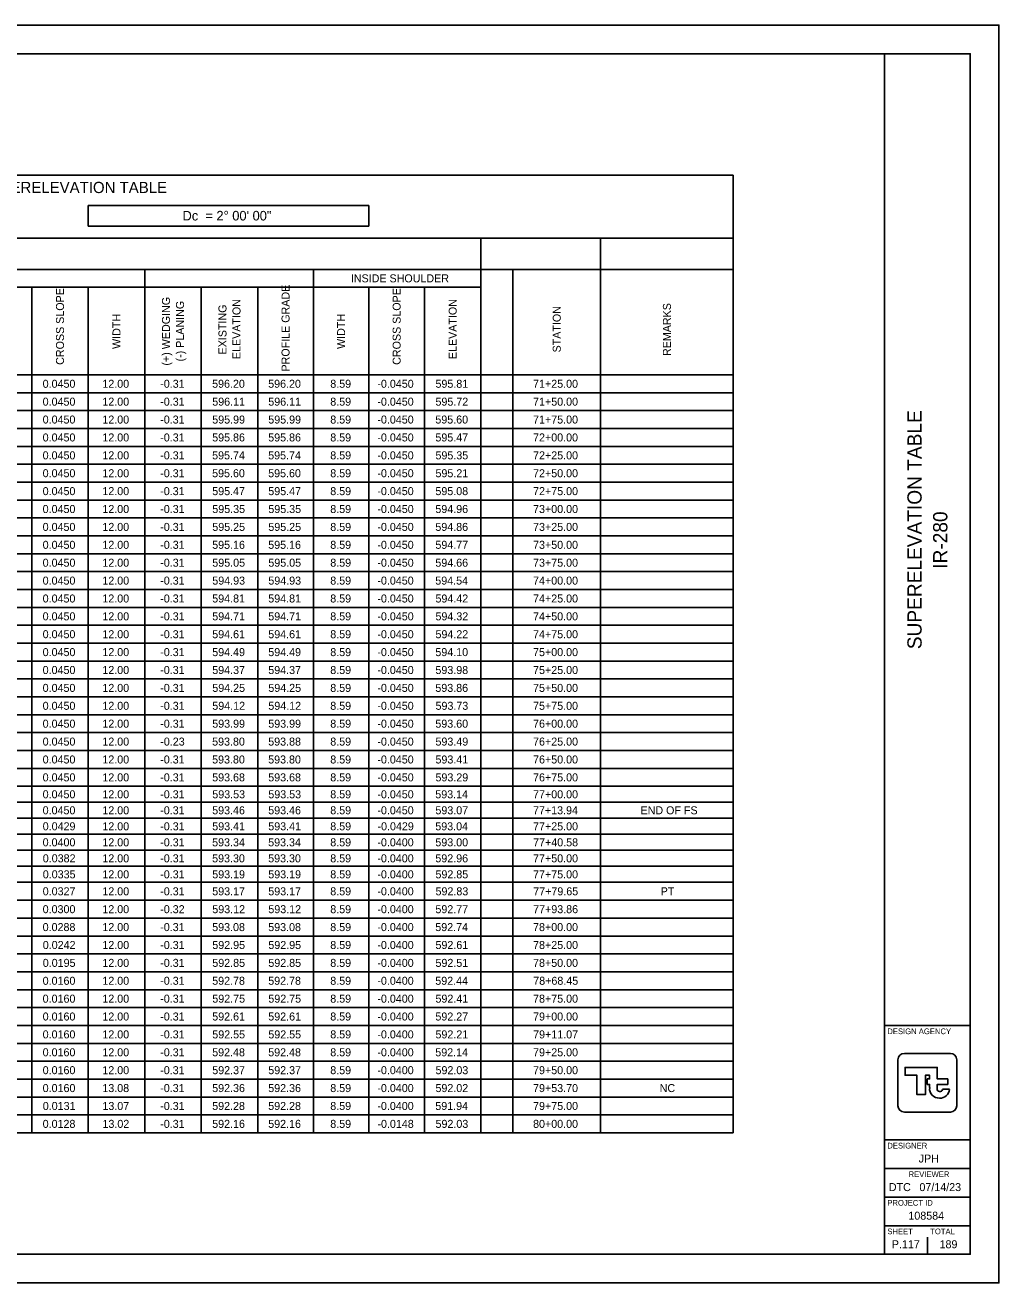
# Model space of a CAD drawing. Extents: x 0 to 34, y 0 to 22.
# Drawn here: x 16.97 to 34, y 0 to 22 of the extents above; entities that cross this region are included whole.
import ezdxf

# ---------------------------------------------------------------- set-up
doc = ezdxf.new("R2010")
doc.units = 0
for name, color, linetype in [('SH_Border', 7, 'Continuous'), ('SH_Cut_Line', 7, 'Continuous'), ('SH_Data', 7, 'Continuous'), ('SH_Text', 7, 'Continuous')]:
    doc.layers.add(name, color=color, linetype=linetype)

msp = doc.modelspace()

# ---------------------------------------------------------------- linework, layer by layer
at = {"layer": 'SH_Border'}
for p, q in [((32, 0.5), (32, 21.5)), ((32, 4.5), (33.5, 4.5)), ((32, 2.5), (33.5, 2.5)), ((32, 2), (33.5, 2)), ((32, 1.5), (33.5, 1.5)), ((32, 1), (33.5, 1))]:
    msp.add_line(p, q, dxfattribs=at)
msp.add_lwpolyline([(1.5, 21.5), (33.5, 21.5), (33.5, 0.5), (1.5, 0.5)], close=True, dxfattribs=at)
at = {"layer": 'SH_Cut_Line'}
msp.add_lwpolyline([(0, 0), (34, 0), (34, 22), (0, 22)], close=True, dxfattribs=at)
at = {"layer": 'SH_Data'}
for p, q in [((32.75, 3.5), (32.75, 3.5)), ((32.791, 3.415), (32.791, 3.415)), ((33.136, 3.385), (33.015, 3.385)), ((32.375, 0.675), (32.375, 0.675)), ((32.75, 0.5), (32.75, 0.8))]:
    msp.add_line(p, q, dxfattribs=at)
for points in [[(32.348, 4.014), (33.152, 4.014)], [(32.236, 3.099), (32.236, 3.901)], [(32.922, 3.399), (32.922, 3.47), (33.107, 3.47), (33.107, 3.568), (32.922, 3.568), (32.922, 3.768), (32.361, 3.768), (32.361, 3.632), (32.566, 3.632), (32.566, 3.294), (32.715, 3.294), (32.715, 3.63), (32.79, 3.63), (32.79, 3.568), (32.748, 3.568), (32.748, 3.47), (32.79, 3.47), (32.79, 3.415), (32.791, 3.415)], [(33.264, 3.901), (33.264, 3.099)], [(33.152, 2.986), (32.348, 2.986)]]:
    msp.add_lwpolyline(points, dxfattribs=at)
for centre, radius, start, end in [((32.348, 3.901), 0.113, 90, 180), ((33.152, 3.901), 0.113, 360, 90), ((32.949, 3.392), 0.16, 171.8856, 274.8323), ((32.968, 3.392), 0.0473, 171.8856, 350.9243), ((32.976, 3.392), 0.16, 265.1677, 357.3201), ((32.348, 3.099), 0.113, 180, 270), ((33.152, 3.099), 0.113, 270, 360)]:
    msp.add_arc(centre, radius, start, end, dxfattribs=at)
at = {"layer": 'SH_Text'}
for p, q in [((4.14, 19.375), (29.356, 19.375)), ((29.356, 19.375), (29.356, 2.624)), ((18.074, 18.848), (22.982, 18.848)), ((18.074, 18.848), (18.074, 18.486)), ((22.982, 18.848), (22.982, 18.486)), ((18.074, 18.486), (22.982, 18.486)), ((4.14, 18.271), (29.356, 18.271)), ((24.942, 18.271), (24.942, 2.624)), ((27.034, 18.271), (27.034, 2.624)), ((4.14, 17.728), (29.356, 17.728)), ((19.062, 17.728), (19.062, 2.624)), ((22.011, 17.728), (22.011, 2.624)), ((25.502, 17.728), (25.502, 2.624)), ((4.14, 17.415), (24.942, 17.415)), ((17.086, 17.415), (17.086, 2.624)), ((18.074, 17.415), (18.074, 2.624)), ((20.051, 17.415), (20.051, 2.624)), ((21.039, 17.415), (21.039, 2.624)), ((22.982, 17.415), (22.982, 2.624)), ((23.954, 17.415), (23.954, 2.624)), ((4.14, 15.883), (29.356, 15.883)), ((4.14, 15.57), (29.356, 15.57)), ((4.14, 15.257), (29.356, 15.257)), ((4.14, 14.944), (29.356, 14.944)), ((4.14, 14.631), (29.356, 14.631)), ((4.14, 14.319), (29.356, 14.319)), ((4.14, 14.006), (29.356, 14.006)), ((4.14, 13.693), (29.356, 13.693)), ((4.14, 13.38), (29.356, 13.38)), ((4.14, 13.067), (29.356, 13.067)), ((4.14, 12.754), (29.356, 12.754)), ((4.14, 12.441), (29.356, 12.441)), ((4.14, 12.128), (29.356, 12.128)), ((4.14, 11.815), (29.356, 11.815)), ((4.14, 11.502), (29.356, 11.502)), ((4.14, 11.189), (29.356, 11.189)), ((4.14, 10.876), (29.356, 10.876)), ((4.14, 10.563), (29.356, 10.563)), ((4.14, 10.25), (29.356, 10.25)), ((4.14, 9.937), (29.356, 9.937)), ((4.14, 9.624), (29.356, 9.624)), ((4.14, 9.311), (29.356, 9.311)), ((4.14, 8.999), (29.356, 8.999)), ((4.14, 8.686), (29.356, 8.686)), ((4.14, 8.406), (29.356, 8.406)), ((4.14, 8.126), (29.356, 8.126)), ((4.14, 7.846), (29.356, 7.846)), ((4.14, 7.566), (29.356, 7.566)), ((4.14, 7.286), (29.356, 7.286)), ((4.14, 7.006), (29.356, 7.006)), ((4.14, 6.693), (29.356, 6.693)), ((4.14, 6.38), (29.356, 6.38)), ((4.14, 6.067), (29.356, 6.067)), ((4.14, 5.754), (29.356, 5.754)), ((4.14, 5.441), (29.356, 5.441)), ((4.14, 5.128), (29.356, 5.128)), ((4.14, 4.815), (29.356, 4.815)), ((4.14, 4.502), (29.356, 4.502)), ((4.14, 4.189), (29.356, 4.189)), ((4.14, 3.876), (29.356, 3.876)), ((4.14, 3.563), (29.356, 3.563)), ((4.14, 3.25), (29.356, 3.25)), ((4.14, 2.937), (29.356, 2.937)), ((4.14, 2.624), (29.356, 2.624))]:
    msp.add_line(p, q, dxfattribs=at)

# ---------------------------------------------------------------- texts
at = {"layer": 'SH_Data'}
for s, p in [('SUPERELEVATION TABLE', (32.65, 11.084)), ('IR-280', (33.1, 12.491))]:
    msp.add_text(s, height=0.25, rotation=90, dxfattribs=at).set_placement(p)
for s, height, p in [('DESIGN AGENCY', 0.1, (32.05, 4.35)), ('DESIGNER', 0.1, (32.05, 2.35)), ('JPH', 0.14, (32.598, 2.105)), ('REVIEWER', 0.1, (32.422, 1.85)), ('DTC', 0.14, (32.076, 1.605)), ('07/14/23', 0.14, (32.611, 1.605)), ('PROJECT ID', 0.1, (32.05, 1.35)), ('108584', 0.14, (32.418, 1.105)), ('SHEET', 0.1, (32.05, 0.85)), ('TOTAL', 0.1, (32.8, 0.85)), ('P.117', 0.14, (32.128, 0.605)), ('189', 0.14, (32.963, 0.605))]:
    msp.add_text(s, height=height, dxfattribs=at).set_placement(p)
at = {"layer": 'SH_Text'}
for s, height, p in [('WOO/LUC-280-06.20/00.00 - SUPERELEVATION TABLE', 0.196, (12.694, 19.063)), ('Dc  = 2° 00\' 00"', 0.168, (19.723, 18.583)), ('INSIDE SHOULDER', 0.14, (22.667, 17.501)), ('0.0450', 0.14, (17.277, 15.657)), ('12.00', 0.14, (18.321, 15.657)), ('-0.31', 0.14, (19.333, 15.657)), ('596.20', 0.14, (20.241, 15.657)), ('596.20', 0.14, (21.221, 15.657)), ('8.59', 0.14, (22.307, 15.657)), ('-0.0450', 0.14, (23.131, 15.657)), ('595.81', 0.14, (24.147, 15.657)), ('71+25.00', 0.14, (25.854, 15.657)), ('0.0450', 0.14, (17.277, 15.344)), ('12.00', 0.14, (18.321, 15.344)), ('-0.31', 0.14, (19.333, 15.344)), ('596.11', 0.14, (20.243, 15.344)), ('596.11', 0.14, (21.223, 15.344)), ('8.59', 0.14, (22.307, 15.344)), ('-0.0450', 0.14, (23.131, 15.344)), ('595.72', 0.14, (24.147, 15.344)), ('71+50.00', 0.14, (25.854, 15.344)), ('0.0450', 0.14, (17.277, 15.031)), ('12.00', 0.14, (18.321, 15.031)), ('-0.31', 0.14, (19.333, 15.031)), ('595.99', 0.14, (20.243, 15.031)), ('595.99', 0.14, (21.223, 15.031)), ('8.59', 0.14, (22.307, 15.031)), ('-0.0450', 0.14, (23.131, 15.031)), ('595.60', 0.14, (24.145, 15.031)), ('71+75.00', 0.14, (25.854, 15.031)), ('0.0450', 0.14, (17.277, 14.718)), ('12.00', 0.14, (18.321, 14.718)), ('-0.31', 0.14, (19.333, 14.718)), ('595.86', 0.14, (20.242, 14.718)), ('595.86', 0.14, (21.222, 14.718)), ('8.59', 0.14, (22.307, 14.718)), ('-0.0450', 0.14, (23.131, 14.718)), ('595.47', 0.14, (24.146, 14.718)), ('72+00.00', 0.14, (25.854, 14.718)), ('0.0450', 0.14, (17.277, 14.405)), ('12.00', 0.14, (18.321, 14.405)), ('-0.31', 0.14, (19.333, 14.405)), ('595.74', 0.14, (20.241, 14.405)), ('595.74', 0.14, (21.221, 14.405)), ('8.59', 0.14, (22.307, 14.405)), ('-0.0450', 0.14, (23.131, 14.405)), ('595.35', 0.14, (24.147, 14.405)), ('72+25.00', 0.14, (25.854, 14.405)), ('0.0450', 0.14, (17.277, 14.092)), ('12.00', 0.14, (18.321, 14.092)), ('-0.31', 0.14, (19.333, 14.092)), ('595.60', 0.14, (20.241, 14.092)), ('595.60', 0.14, (21.221, 14.092)), ('8.59', 0.14, (22.307, 14.092)), ('-0.0450', 0.14, (23.131, 14.092)), ('595.21', 0.14, (24.147, 14.092)), ('72+50.00', 0.14, (25.854, 14.092)), ('0.0450', 0.14, (17.277, 13.779)), ('12.00', 0.14, (18.321, 13.779)), ('-0.31', 0.14, (19.333, 13.779)), ('595.47', 0.14, (20.243, 13.779)), ('595.47', 0.14, (21.223, 13.779)), ('8.59', 0.14, (22.307, 13.779)), ('-0.0450', 0.14, (23.131, 13.779)), ('595.08', 0.14, (24.146, 13.779)), ('72+75.00', 0.14, (25.854, 13.779)), ('0.0450', 0.14, (17.277, 13.466)), ('12.00', 0.14, (18.321, 13.466)), ('-0.31', 0.14, (19.333, 13.466)), ('595.35', 0.14, (20.244, 13.466)), ('595.35', 0.14, (21.224, 13.466)), ('8.59', 0.14, (22.307, 13.466)), ('-0.0450', 0.14, (23.131, 13.466)), ('594.96', 0.14, (24.145, 13.466)), ('73+00.00', 0.14, (25.854, 13.466)), ('0.0450', 0.14, (17.277, 13.153)), ('12.00', 0.14, (18.321, 13.153)), ('-0.31', 0.14, (19.333, 13.153)), ('595.25', 0.14, (20.244, 13.153)), ('595.25', 0.14, (21.224, 13.153)), ('8.59', 0.14, (22.307, 13.153)), ('-0.0450', 0.14, (23.131, 13.153)), ('594.86', 0.14, (24.145, 13.153)), ('73+25.00', 0.14, (25.854, 13.153)), ('0.0450', 0.14, (17.277, 12.84)), ('12.00', 0.14, (18.321, 12.84)), ('-0.31', 0.14, (19.333, 12.84)), ('595.16', 0.14, (20.242, 12.84)), ('595.16', 0.14, (21.222, 12.84)), ('8.59', 0.14, (22.307, 12.84)), ('-0.0450', 0.14, (23.131, 12.84)), ('594.77', 0.14, (24.146, 12.84)), ('73+50.00', 0.14, (25.854, 12.84)), ('0.0450', 0.14, (17.277, 12.527)), ('12.00', 0.14, (18.321, 12.527)), ('-0.31', 0.14, (19.333, 12.527)), ('595.05', 0.14, (20.244, 12.527)), ('595.05', 0.14, (21.224, 12.527)), ('8.59', 0.14, (22.307, 12.527)), ('-0.0450', 0.14, (23.131, 12.527)), ('594.66', 0.14, (24.145, 12.527)), ('73+75.00', 0.14, (25.854, 12.527)), ('0.0450', 0.14, (17.277, 12.214)), ('12.00', 0.14, (18.321, 12.214)), ('-0.31', 0.14, (19.333, 12.214)), ('594.93', 0.14, (20.244, 12.214)), ('594.93', 0.14, (21.224, 12.214)), ('8.59', 0.14, (22.307, 12.214)), ('-0.0450', 0.14, (23.131, 12.214)), ('594.54', 0.14, (24.144, 12.214)), ('74+00.00', 0.14, (25.854, 12.214)), ('0.0450', 0.14, (17.277, 11.901)), ('12.00', 0.14, (18.321, 11.901)), ('-0.31', 0.14, (19.333, 11.901)), ('594.81', 0.14, (20.243, 11.901)), ('594.81', 0.14, (21.223, 11.901)), ('8.59', 0.14, (22.307, 11.901)), ('-0.0450', 0.14, (23.131, 11.901)), ('594.42', 0.14, (24.147, 11.901)), ('74+25.00', 0.14, (25.854, 11.901)), ('0.0450', 0.14, (17.277, 11.589)), ('12.00', 0.14, (18.321, 11.589)), ('-0.31', 0.14, (19.333, 11.589)), ('594.71', 0.14, (20.243, 11.589)), ('594.71', 0.14, (21.223, 11.589)), ('8.59', 0.14, (22.307, 11.589)), ('-0.0450', 0.14, (23.131, 11.589)), ('594.32', 0.14, (24.147, 11.589)), ('74+50.00', 0.14, (25.854, 11.589)), ('0.0450', 0.14, (17.277, 11.276)), ('12.00', 0.14, (18.321, 11.276)), ('-0.31', 0.14, (19.333, 11.276)), ('594.61', 0.14, (20.243, 11.276)), ('594.61', 0.14, (21.223, 11.276)), ('8.59', 0.14, (22.307, 11.276)), ('-0.0450', 0.14, (23.131, 11.276)), ('594.22', 0.14, (24.147, 11.276)), ('74+75.00', 0.14, (25.854, 11.276)), ('0.0450', 0.14, (17.277, 10.963)), ('12.00', 0.14, (18.321, 10.963)), ('-0.31', 0.14, (19.333, 10.963)), ('594.49', 0.14, (20.243, 10.963)), ('594.49', 0.14, (21.223, 10.963)), ('8.59', 0.14, (22.307, 10.963)), ('-0.0450', 0.14, (23.131, 10.963)), ('594.10', 0.14, (24.145, 10.963)), ('75+00.00', 0.14, (25.854, 10.963)), ('0.0450', 0.14, (17.277, 10.65)), ('12.00', 0.14, (18.321, 10.65)), ('-0.31', 0.14, (19.333, 10.65)), ('594.37', 0.14, (20.243, 10.65)), ('594.37', 0.14, (21.223, 10.65)), ('8.59', 0.14, (22.307, 10.65)), ('-0.0450', 0.14, (23.131, 10.65)), ('593.98', 0.14, (24.146, 10.65)), ('75+25.00', 0.14, (25.854, 10.65)), ('0.0450', 0.14, (17.277, 10.337)), ('12.00', 0.14, (18.321, 10.337)), ('-0.31', 0.14, (19.333, 10.337)), ('594.25', 0.14, (20.244, 10.337)), ('594.25', 0.14, (21.224, 10.337)), ('8.59', 0.14, (22.307, 10.337)), ('-0.0450', 0.14, (23.131, 10.337)), ('593.86', 0.14, (24.145, 10.337)), ('75+50.00', 0.14, (25.854, 10.337)), ('0.0450', 0.14, (17.277, 10.024)), ('12.00', 0.14, (18.321, 10.024)), ('-0.31', 0.14, (19.333, 10.024)), ('594.12', 0.14, (20.244, 10.024)), ('594.12', 0.14, (21.224, 10.024)), ('8.59', 0.14, (22.307, 10.024)), ('-0.0450', 0.14, (23.131, 10.024)), ('593.73', 0.14, (24.148, 10.024)), ('75+75.00', 0.14, (25.854, 10.024)), ('0.0450', 0.14, (17.277, 9.711)), ('12.00', 0.14, (18.321, 9.711)), ('-0.31', 0.14, (19.333, 9.711)), ('593.99', 0.14, (20.243, 9.711)), ('593.99', 0.14, (21.223, 9.711)), ('8.59', 0.14, (22.307, 9.711)), ('-0.0450', 0.14, (23.131, 9.711)), ('593.60', 0.14, (24.145, 9.711)), ('76+00.00', 0.14, (25.854, 9.711)), ('0.0450', 0.14, (17.277, 9.398)), ('12.00', 0.14, (18.321, 9.398)), ('-0.23', 0.14, (19.334, 9.398)), ('593.80', 0.14, (20.241, 9.398)), ('593.88', 0.14, (21.222, 9.398)), ('8.59', 0.14, (22.307, 9.398)), ('-0.0450', 0.14, (23.131, 9.398)), ('593.49', 0.14, (24.147, 9.398)), ('76+25.00', 0.14, (25.854, 9.398)), ('0.0450', 0.14, (17.277, 9.085)), ('12.00', 0.14, (18.321, 9.085)), ('-0.31', 0.14, (19.333, 9.085)), ('593.80', 0.14, (20.241, 9.085)), ('593.80', 0.14, (21.221, 9.085)), ('8.59', 0.14, (22.307, 9.085)), ('-0.0450', 0.14, (23.131, 9.085)), ('593.41', 0.14, (24.147, 9.085)), ('76+50.00', 0.14, (25.854, 9.085)), ('0.0450', 0.14, (17.277, 8.772)), ('12.00', 0.14, (18.321, 8.772)), ('-0.31', 0.14, (19.333, 8.772)), ('593.68', 0.14, (20.242, 8.772)), ('593.68', 0.14, (21.222, 8.772)), ('8.59', 0.14, (22.307, 8.772)), ('-0.0450', 0.14, (23.131, 8.772)), ('593.29', 0.14, (24.147, 8.772)), ('76+75.00', 0.14, (25.854, 8.772)), ('0.0450', 0.14, (17.277, 8.476)), ('12.00', 0.14, (18.321, 8.476)), ('-0.31', 0.14, (19.333, 8.476)), ('593.53', 0.14, (20.244, 8.476)), ('593.53', 0.14, (21.224, 8.476)), ('8.59', 0.14, (22.307, 8.476)), ('-0.0450', 0.14, (23.131, 8.476)), ('593.14', 0.14, (24.144, 8.476)), ('77+00.00', 0.14, (25.854, 8.476)), ('0.0450', 0.14, (17.277, 8.196)), ('12.00', 0.14, (18.321, 8.196)), ('-0.31', 0.14, (19.333, 8.196)), ('593.46', 0.14, (20.242, 8.196)), ('593.46', 0.14, (21.222, 8.196)), ('8.59', 0.14, (22.307, 8.196)), ('-0.0450', 0.14, (23.131, 8.196)), ('593.07', 0.14, (24.146, 8.196)), ('77+13.94', 0.14, (25.853, 8.196)), ('END OF FS', 0.14, (27.733, 8.196)), ('0.0429', 0.14, (17.278, 7.916)), ('12.00', 0.14, (18.321, 7.916)), ('-0.31', 0.14, (19.333, 7.916)), ('593.41', 0.14, (20.243, 7.916)), ('593.41', 0.14, (21.223, 7.916)), ('8.59', 0.14, (22.307, 7.916)), ('-0.0429', 0.14, (23.133, 7.916)), ('593.04', 0.14, (24.144, 7.916)), ('77+25.00', 0.14, (25.854, 7.916)), ('0.0400', 0.14, (17.277, 7.636)), ('12.00', 0.14, (18.321, 7.636)), ('-0.31', 0.14, (19.333, 7.636)), ('593.34', 0.14, (20.241, 7.636)), ('593.34', 0.14, (21.221, 7.636)), ('8.59', 0.14, (22.307, 7.636)), ('-0.0400', 0.14, (23.131, 7.636)), ('593.00', 0.14, (24.145, 7.636)), ('77+40.58', 0.14, (25.855, 7.636)), ('0.0382', 0.14, (17.279, 7.356)), ('12.00', 0.14, (18.321, 7.356)), ('-0.31', 0.14, (19.333, 7.356)), ('593.30', 0.14, (20.241, 7.356)), ('593.30', 0.14, (21.221, 7.356)), ('8.59', 0.14, (22.307, 7.356)), ('-0.0400', 0.14, (23.131, 7.356)), ('592.96', 0.14, (24.145, 7.356)), ('77+50.00', 0.14, (25.854, 7.356)), ('0.0335', 0.14, (17.279, 7.076)), ('12.00', 0.14, (18.321, 7.076)), ('-0.31', 0.14, (19.333, 7.076)), ('593.19', 0.14, (20.243, 7.076)), ('593.19', 0.14, (21.223, 7.076)), ('8.59', 0.14, (22.307, 7.076)), ('-0.0400', 0.14, (23.131, 7.076)), ('592.85', 0.14, (24.147, 7.076)), ('77+75.00', 0.14, (25.854, 7.076)), ('0.0327', 0.14, (17.278, 6.779)), ('12.00', 0.14, (18.321, 6.779)), ('-0.31', 0.14, (19.333, 6.779)), ('593.17', 0.14, (20.243, 6.779)), ('593.17', 0.14, (21.223, 6.779)), ('8.59', 0.14, (22.307, 6.779)), ('-0.0400', 0.14, (23.131, 6.779)), ('592.83', 0.14, (24.148, 6.779)), ('77+79.65', 0.14, (25.857, 6.779)), ('PT', 0.14, (28.086, 6.779)), ('0.0300', 0.14, (17.277, 6.466)), ('12.00', 0.14, (18.321, 6.466)), ('-0.32', 0.14, (19.333, 6.466)), ('593.12', 0.14, (20.244, 6.466)), ('593.12', 0.14, (21.224, 6.466)), ('8.59', 0.14, (22.307, 6.466)), ('-0.0400', 0.14, (23.131, 6.466)), ('592.77', 0.14, (24.146, 6.466)), ('77+93.86', 0.14, (25.855, 6.466)), ('0.0288', 0.14, (17.277, 6.153)), ('12.00', 0.14, (18.321, 6.153)), ('-0.31', 0.14, (19.333, 6.153)), ('593.08', 0.14, (20.242, 6.153)), ('593.08', 0.14, (21.222, 6.153)), ('8.59', 0.14, (22.307, 6.153)), ('-0.0400', 0.14, (23.131, 6.153)), ('592.74', 0.14, (24.144, 6.153)), ('78+00.00', 0.14, (25.854, 6.153)), ('0.0242', 0.14, (17.279, 5.84)), ('12.00', 0.14, (18.321, 5.84)), ('-0.31', 0.14, (19.333, 5.84)), ('592.95', 0.14, (20.244, 5.84)), ('592.95', 0.14, (21.224, 5.84)), ('8.59', 0.14, (22.307, 5.84)), ('-0.0400', 0.14, (23.131, 5.84)), ('592.61', 0.14, (24.147, 5.84)), ('78+25.00', 0.14, (25.854, 5.84)), ('0.0195', 0.14, (17.279, 5.527)), ('12.00', 0.14, (18.321, 5.527)), ('-0.31', 0.14, (19.333, 5.527)), ('592.85', 0.14, (20.244, 5.527)), ('592.85', 0.14, (21.224, 5.527)), ('8.59', 0.14, (22.307, 5.527)), ('-0.0400', 0.14, (23.131, 5.527)), ('592.51', 0.14, (24.147, 5.527)), ('78+50.00', 0.14, (25.854, 5.527)), ('0.0160', 0.14, (17.277, 5.214)), ('12.00', 0.14, (18.321, 5.214)), ('-0.31', 0.14, (19.333, 5.214)), ('592.78', 0.14, (20.242, 5.214)), ('592.78', 0.14, (21.222, 5.214)), ('8.59', 0.14, (22.307, 5.214)), ('-0.0400', 0.14, (23.131, 5.214)), ('592.44', 0.14, (24.144, 5.214)), ('78+68.45', 0.14, (25.857, 5.214)), ('0.0160', 0.14, (17.277, 4.901)), ('12.00', 0.14, (18.321, 4.901)), ('-0.31', 0.14, (19.333, 4.901)), ('592.75', 0.14, (20.244, 4.901)), ('592.75', 0.14, (21.224, 4.901)), ('8.59', 0.14, (22.307, 4.901)), ('-0.0400', 0.14, (23.131, 4.901)), ('592.41', 0.14, (24.147, 4.901)), ('78+75.00', 0.14, (25.854, 4.901)), ('0.0160', 0.14, (17.277, 4.589)), ('12.00', 0.14, (18.321, 4.589)), ('-0.31', 0.14, (19.333, 4.589)), ('592.61', 0.14, (20.243, 4.589)), ('592.61', 0.14, (21.223, 4.589)), ('8.59', 0.14, (22.307, 4.589)), ('-0.0400', 0.14, (23.131, 4.589)), ('592.27', 0.14, (24.146, 4.589)), ('79+00.00', 0.14, (25.854, 4.589)), ('0.0160', 0.14, (17.277, 4.276)), ('12.00', 0.14, (18.321, 4.276)), ('-0.31', 0.14, (19.333, 4.276)), ('592.55', 0.14, (20.244, 4.276)), ('592.55', 0.14, (21.224, 4.276)), ('8.59', 0.14, (22.307, 4.276)), ('-0.0400', 0.14, (23.131, 4.276)), ('592.21', 0.14, (24.147, 4.276)), ('79+11.07', 0.14, (25.855, 4.276)), ('0.0160', 0.14, (17.277, 3.963)), ('12.00', 0.14, (18.321, 3.963)), ('-0.31', 0.14, (19.333, 3.963)), ('592.48', 0.14, (20.242, 3.963)), ('592.48', 0.14, (21.222, 3.963)), ('8.59', 0.14, (22.307, 3.963)), ('-0.0400', 0.14, (23.131, 3.963)), ('592.14', 0.14, (24.144, 3.963)), ('79+25.00', 0.14, (25.854, 3.963)), ('0.0160', 0.14, (17.277, 3.65)), ('12.00', 0.14, (18.321, 3.65)), ('-0.31', 0.14, (19.333, 3.65)), ('592.37', 0.14, (20.243, 3.65)), ('592.37', 0.14, (21.223, 3.65)), ('8.59', 0.14, (22.307, 3.65)), ('-0.0400', 0.14, (23.131, 3.65)), ('592.03', 0.14, (24.148, 3.65)), ('79+50.00', 0.14, (25.854, 3.65)), ('0.0160', 0.14, (17.277, 3.337)), ('13.08', 0.14, (18.321, 3.337)), ('-0.31', 0.14, (19.333, 3.337)), ('592.36', 0.14, (20.242, 3.337)), ('592.36', 0.14, (21.222, 3.337)), ('8.59', 0.14, (22.307, 3.337)), ('-0.0400', 0.14, (23.131, 3.337)), ('592.02', 0.14, (24.147, 3.337)), ('79+53.70', 0.14, (25.854, 3.337)), ('NC', 0.14, (28.068, 3.337)), ('0.0131', 0.14, (17.279, 3.024)), ('13.07', 0.14, (18.322, 3.024)), ('-0.31', 0.14, (19.333, 3.024)), ('592.28', 0.14, (20.242, 3.024)), ('592.28', 0.14, (21.222, 3.024)), ('8.59', 0.14, (22.307, 3.024)), ('-0.0400', 0.14, (23.131, 3.024)), ('591.94', 0.14, (24.144, 3.024)), ('79+75.00', 0.14, (25.854, 3.024)), ('0.0128', 0.14, (17.277, 2.711)), ('13.02', 0.14, (18.323, 2.711)), ('-0.31', 0.14, (19.333, 2.711)), ('592.16', 0.14, (20.242, 2.711)), ('592.16', 0.14, (21.222, 2.711)), ('8.59', 0.14, (22.307, 2.711)), ('-0.0148', 0.14, (23.132, 2.711)), ('592.03', 0.14, (24.148, 2.711)), ('80+00.00', 0.14, (25.854, 2.711))]:
    msp.add_text(s, height=height, dxfattribs=at).set_placement(p)
for s, p in [('CROSS SLOPE', (17.65, 16.058)), ('PROFILE GRADE', (21.595, 15.941)), ('CROSS SLOPE', (23.538, 16.058)), ('(+) WEDGING', (19.504, 16.045)), ('(-) PLANING', (19.749, 16.117)), ('ELEVATION', (20.737, 16.158)), ('ELEVATION', (24.518, 16.158)), ('EXISTING ', (20.492, 16.24)), ('STATION', (26.338, 16.275)), ('REMARKS', (28.265, 16.212)), ('WIDTH', (18.638, 16.336)), ('WIDTH', (22.566, 16.336))]:
    msp.add_text(s, height=0.14, rotation=90, dxfattribs=at).set_placement(p)

doc.saveas('drawing.dxf')
